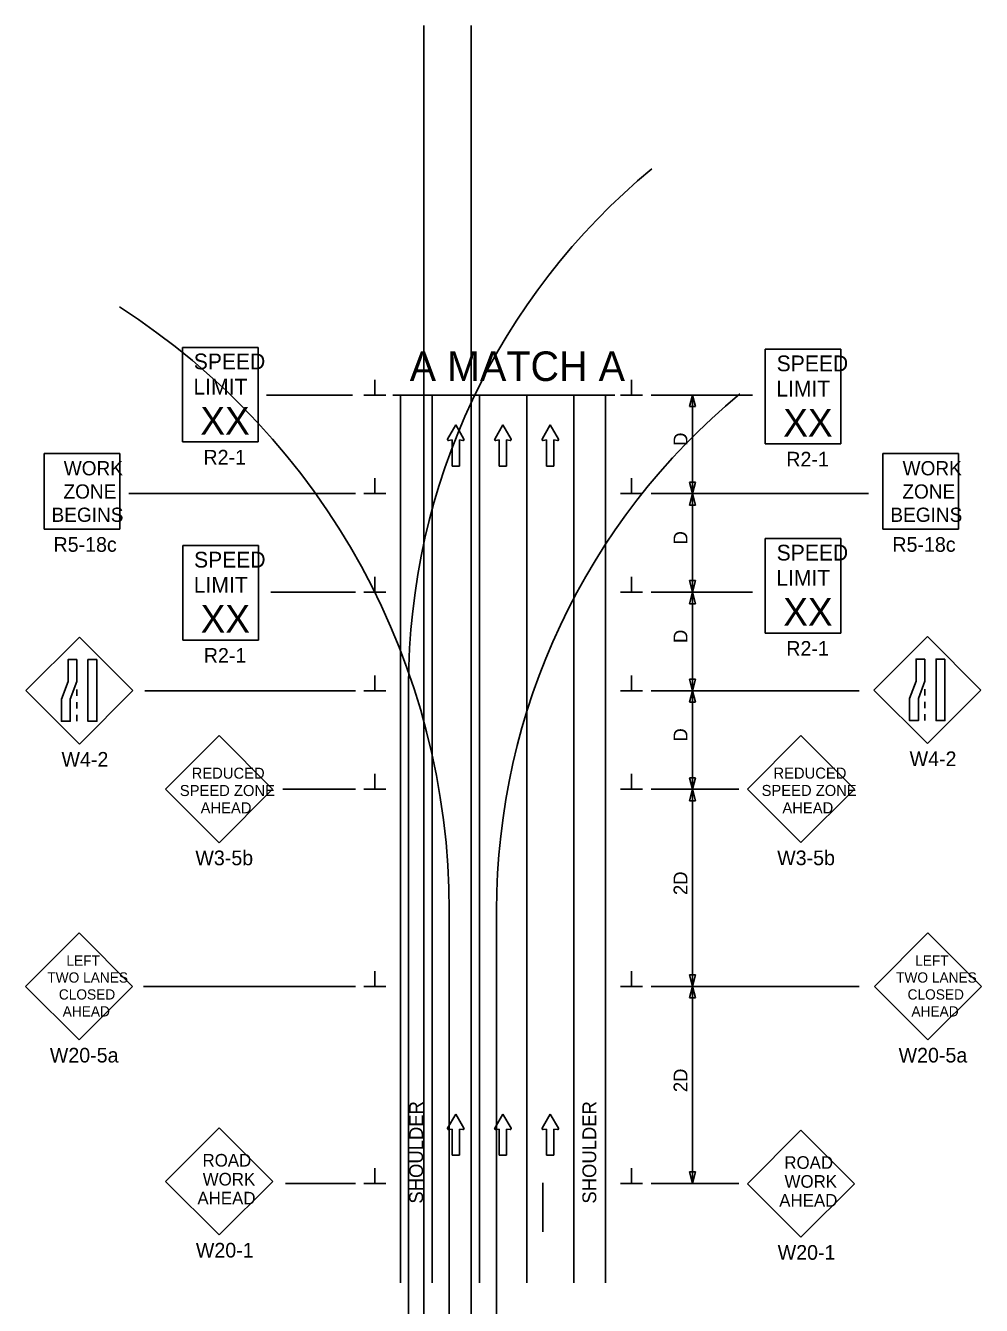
# Model space of a CAD drawing. Extents: x 16452 to 19508, y 5713 to 7079.
# Drawn here: x 17853 to 18337, y 6430 to 7079 of the extents above; entities that cross this region are included whole.
import ezdxf

# ---------------------------------------------------------------- set-up
doc = ezdxf.new("R2010")
doc.units = 0
for name, color, linetype in [('ALI_LEGAL_EX', 7, 'Continuous'), ('MT_SCRATCH_LEVEL_E', 7, 'Continuous'), ('PAVT_EDGE_EX', 7, 'Continuous'), ('TRAFFIC_SIGNS_PR', 7, 'Continuous'), ('TYPICAL_TEXT_DIMEN_PR', 7, 'Continuous')]:
    doc.layers.add(name, color=color, linetype=linetype)

msp = doc.modelspace()

# ---------------------------------------------------------------- linework, layer by layer
at = {"layer": 'ALI_LEGAL_EX'}
for p, q in [((18054.48, 7078.99), (18054.48, 6260.86)), ((18078.48, 7078.99), (18078.48, 6260.86)), ((18054.48, 6981.91), (18054.48, 6118)), ((18078.48, 6981.91), (18078.48, 6118)), ((18082.72, 6441.2), (18082.72, 6891.55)), ((18106.72, 6441.2), (18106.72, 6891.55)), ((18046.81, 6243.91), (18046.81, 6744.25)), ((18067.45, 6129.67), (18067.45, 6630.02)), ((18091.45, 6129.67), (18091.45, 6630.02))]:
    msp.add_line(p, q, dxfattribs=at)
for points in [[(18082.81, 6871.42), (18082.81, 6846.42)], [(18082.72, 6841.2), (18082.72, 6866.2)], [(18106.72, 6841.2), (18106.72, 6866.2)], [(18082.72, 6741.2), (18082.72, 6766.2)], [(18106.72, 6741.2), (18106.72, 6766.2)], [(18082.72, 6641.2), (18082.72, 6666.2)], [(18106.72, 6641.2), (18106.72, 6666.2)], [(18082.72, 6541.2), (18082.72, 6566.2)], [(18106.72, 6541.2), (18106.72, 6566.2)], [(18082.81, 6521.86), (18082.81, 6496.86)], [(18114.95, 6491.99), (18114.95, 6466.99)], [(18082.72, 6441.2), (18082.72, 6466.2)], [(18106.72, 6441.2), (18106.72, 6466.2)]]:
    msp.add_lwpolyline(points, dxfattribs=at)
for centre, radius, start, end in [((18386.81, 6744.25), 340, 129.56655, 180), ((17703.45, 6630.02), 364, 0, 57.29578), ((18431.45, 6630.02), 340, 129.56655, 180)]:
    msp.add_arc(centre, radius, start, end, dxfattribs=at)
at = {"layer": 'MT_SCRATCH_LEVEL_E'}
for p, q in [((18070.73, 6876.38), (18066.62, 6869.14)), ((18074.88, 6869.14), (18070.73, 6876.38)), ((18094.64, 6876.38), (18090.53, 6869.14)), ((18098.78, 6869.14), (18094.64, 6876.38)), ((18118.69, 6876.38), (18114.58, 6869.14)), ((18122.84, 6869.14), (18118.69, 6876.38)), ((18067.1, 6868.46), (18068.88, 6868.77)), ((18068.88, 6868.77), (18068.88, 6855.51)), ((18072.62, 6855.51), (18072.62, 6868.77)), ((18072.62, 6868.77), (18074.4, 6868.46)), ((18091.01, 6868.46), (18092.78, 6868.77)), ((18092.78, 6868.77), (18092.78, 6855.51)), ((18096.53, 6855.51), (18096.53, 6868.77)), ((18096.53, 6868.77), (18098.3, 6868.46)), ((18115.06, 6868.46), (18116.84, 6868.77)), ((18116.84, 6868.77), (18116.84, 6855.51)), ((18120.58, 6855.51), (18120.58, 6868.77)), ((18120.58, 6868.77), (18122.36, 6868.46)), ((18068.88, 6855.51), (18072.62, 6855.51)), ((18092.78, 6855.51), (18096.53, 6855.51)), ((18116.84, 6855.51), (18120.58, 6855.51)), ((18070.73, 6526.83), (18066.62, 6519.59)), ((18074.88, 6519.59), (18070.73, 6526.83)), ((18094.64, 6526.83), (18090.53, 6519.59)), ((18098.78, 6519.59), (18094.64, 6526.83)), ((18118.69, 6526.83), (18114.58, 6519.59)), ((18122.84, 6519.59), (18118.69, 6526.83)), ((18067.1, 6518.9), (18068.88, 6519.22)), ((18068.88, 6519.22), (18068.88, 6505.96)), ((18072.62, 6505.96), (18072.62, 6519.22)), ((18072.62, 6519.22), (18074.4, 6518.9)), ((18091.01, 6518.9), (18092.78, 6519.22)), ((18092.78, 6519.22), (18092.78, 6505.96)), ((18096.53, 6505.96), (18096.53, 6519.22)), ((18096.53, 6519.22), (18098.3, 6518.9)), ((18115.06, 6518.9), (18116.84, 6519.22)), ((18116.84, 6519.22), (18116.84, 6505.96)), ((18120.58, 6505.96), (18120.58, 6519.22)), ((18120.58, 6519.22), (18122.36, 6518.9)), ((18068.88, 6505.96), (18072.62, 6505.96)), ((18092.78, 6505.96), (18096.53, 6505.96)), ((18116.84, 6505.96), (18120.58, 6505.96))]:
    msp.add_line(p, q, dxfattribs=at)
for centre, start, end in [((18067.03, 6868.91), 150.42484, 279.96381), ((18074.47, 6868.91), 260.03619, 29.77312), ((18090.93, 6868.91), 150.42484, 279.96381), ((18098.37, 6868.91), 260.03619, 29.77312), ((18114.99, 6868.91), 150.42484, 279.96381), ((18122.43, 6868.91), 260.03619, 29.77312), ((18067.03, 6519.36), 150.42484, 279.96381), ((18074.47, 6519.36), 260.03619, 29.77312), ((18090.93, 6519.36), 150.42484, 279.96381), ((18098.37, 6519.36), 260.03619, 29.77312), ((18114.99, 6519.36), 150.42484, 279.96381), ((18122.43, 6519.36), 260.03619, 29.77312)]:
    msp.add_arc(centre, 0.463, start, end, dxfattribs=at)
at = {"layer": 'PAVT_EDGE_EX'}
for p, q in [((18042.72, 6891.55), (18042.72, 6441.2)), ((18058.72, 6891.55), (18058.72, 6441.2)), ((18130.72, 6891.55), (18130.72, 6441.2)), ((18146.72, 6891.55), (18146.72, 6441.2))]:
    msp.add_line(p, q, dxfattribs=at)
at = {"layer": 'TRAFFIC_SIGNS_PR'}
for p, q in [((17932.09, 6915.75), (17970.49, 6915.75)), ((17932.09, 6867.75), (17932.09, 6915.75)), ((17970.49, 6867.75), (17970.49, 6915.75)), ((18227.77, 6914.76), (18266.17, 6914.76)), ((18227.77, 6866.76), (18227.77, 6914.76)), ((18266.17, 6866.76), (18266.17, 6914.76)), ((17932.09, 6867.75), (17970.49, 6867.75)), ((18227.77, 6866.76), (18266.17, 6866.76)), ((17861.89, 6823.48), (17861.89, 6861.88)), ((17861.89, 6861.88), (17900.29, 6861.88)), ((17900.29, 6823.48), (17900.29, 6861.88)), ((18287.43, 6823.48), (18287.43, 6861.88)), ((18287.43, 6861.88), (18325.83, 6861.88)), ((18325.83, 6823.48), (18325.83, 6861.88)), ((17861.89, 6823.48), (17900.29, 6823.48)), ((18227.77, 6818.77), (18266.17, 6818.77)), ((18227.77, 6770.77), (18227.77, 6818.77)), ((18266.17, 6770.77), (18266.17, 6818.77)), ((18287.43, 6823.48), (18325.83, 6823.48)), ((17932.24, 6815.2), (17970.64, 6815.2)), ((17932.24, 6767.2), (17932.24, 6815.2)), ((17970.64, 6767.2), (17970.64, 6815.2)), ((17879.8, 6768.78), (17852.64, 6741.63)), ((17906.95, 6741.63), (17879.8, 6768.78)), ((17932.24, 6767.2), (17970.64, 6767.2)), ((18227.77, 6770.77), (18266.17, 6770.77)), ((18310.03, 6769.06), (18282.87, 6741.91)), ((18337.18, 6741.91), (18310.03, 6769.06)), ((17852.64, 6741.63), (17879.8, 6714.47)), ((17878.55, 6742.12), (17878.55, 6738.92)), ((17879.8, 6714.47), (17906.95, 6741.63)), ((18282.87, 6741.91), (18310.03, 6714.76)), ((18308.78, 6742.4), (18308.78, 6739.2)), ((18310.03, 6714.76), (18337.18, 6741.91)), ((17878.55, 6735.72), (17878.55, 6732.52)), ((18308.78, 6736), (18308.78, 6732.8)), ((17878.55, 6729.32), (17878.55, 6726.12)), ((18308.78, 6729.6), (18308.78, 6726.4)), ((17950.71, 6718.78), (17923.56, 6691.63)), ((17977.86, 6691.63), (17950.71, 6718.78)), ((18245.84, 6718.81), (18218.69, 6691.66)), ((18273, 6691.66), (18245.84, 6718.81)), ((17923.56, 6691.63), (17950.71, 6664.47)), ((17950.71, 6664.47), (17977.86, 6691.63)), ((18218.69, 6691.66), (18245.84, 6664.5)), ((18245.84, 6664.5), (18273, 6691.66)), ((17879.69, 6618.7), (17852.54, 6591.55)), ((17906.84, 6591.55), (17879.69, 6618.7)), ((18310.24, 6618.7), (18283.09, 6591.55)), ((18337.39, 6591.55), (18310.24, 6618.7)), ((17852.54, 6591.55), (17879.69, 6564.4)), ((17879.69, 6564.4), (17906.84, 6591.55)), ((18283.09, 6591.55), (18310.24, 6564.4)), ((18310.24, 6564.4), (18337.39, 6591.55)), ((17950.74, 6519.77), (17923.59, 6492.62)), ((17977.9, 6492.62), (17950.74, 6519.77)), ((18245.88, 6518.64), (18218.73, 6491.48)), ((18273.03, 6491.48), (18245.88, 6518.64)), ((17923.59, 6492.62), (17950.74, 6465.47)), ((17950.74, 6465.47), (17977.9, 6492.62)), ((18218.73, 6491.48), (18245.88, 6464.33)), ((18245.88, 6464.33), (18273.03, 6491.48))]:
    msp.add_line(p, q, dxfattribs=at)
for points in [[(17878.55, 6757.36), (17878.55, 6746.18), (17875.2, 6737.3), (17875.2, 6726.12), (17870.71, 6726.12), (17870.71, 6737.3), (17874.05, 6746.18), (17874.05, 6757.36)], [(17888.68, 6757.36), (17888.68, 6726.12), (17884.19, 6726.12), (17884.19, 6757.36)], [(18308.78, 6757.65), (18308.78, 6746.46), (18305.43, 6737.58), (18305.43, 6726.4), (18300.94, 6726.4), (18300.94, 6737.58), (18304.28, 6746.46), (18304.28, 6757.65)], [(18318.91, 6757.65), (18318.91, 6726.4), (18314.42, 6726.4), (18314.42, 6757.65)]]:
    msp.add_lwpolyline(points, close=True, dxfattribs=at)
at = {"layer": 'TYPICAL_TEXT_DIMEN_PR'}
for p, q in [((18029.69, 6891.55), (18029.69, 6899.34)), ((18159.94, 6891.55), (18159.94, 6899.34)), ((17974.8, 6891.55), (18018.42, 6891.55)), ((18024.06, 6891.55), (18035.31, 6891.55)), ((18038.79, 6891.55), (18151.44, 6891.55)), ((18165.56, 6891.55), (18154.31, 6891.55)), ((18169.81, 6891.55), (18221.23, 6891.55)), ((18189.24, 6885.69), (18190.81, 6891.55)), ((18190.81, 6891.55), (18190.81, 6841.55)), ((18190.81, 6891.55), (18192.39, 6885.69)), ((18190.81, 6885.69), (18189.24, 6885.69)), ((18192.39, 6885.69), (18190.81, 6885.69)), ((18029.69, 6841.55), (18029.69, 6849.34)), ((18159.94, 6841.55), (18159.94, 6849.34)), ((18190.81, 6841.55), (18189.24, 6847.41)), ((18189.24, 6847.41), (18190.81, 6847.41)), ((18190.81, 6847.41), (18192.39, 6847.41)), ((18192.39, 6847.41), (18190.81, 6841.55)), ((18019.81, 6841.55), (17904.88, 6841.55)), ((18024.06, 6841.55), (18035.31, 6841.55)), ((18165.56, 6841.55), (18154.31, 6841.55)), ((18169.81, 6841.55), (18280.08, 6841.55)), ((18189.24, 6835.69), (18190.81, 6841.55)), ((18190.81, 6841.55), (18192.39, 6835.69)), ((18190.81, 6841.55), (18190.81, 6791.55)), ((18190.81, 6835.69), (18189.24, 6835.69)), ((18192.39, 6835.69), (18190.81, 6835.69)), ((18029.69, 6791.55), (18029.69, 6799.34)), ((18159.94, 6791.55), (18159.94, 6799.34)), ((18019.81, 6791.55), (17976.96, 6791.55)), ((18024.06, 6791.55), (18035.31, 6791.55)), ((18165.56, 6791.55), (18154.31, 6791.55)), ((18169.81, 6791.55), (18221.23, 6791.55)), ((18190.81, 6791.55), (18189.24, 6797.41)), ((18189.24, 6797.41), (18190.81, 6797.41)), ((18189.24, 6785.69), (18190.81, 6791.55)), ((18190.81, 6797.41), (18192.39, 6797.41)), ((18192.39, 6797.41), (18190.81, 6791.55)), ((18190.81, 6791.55), (18190.81, 6741.55)), ((18190.81, 6791.55), (18192.39, 6785.69)), ((18190.81, 6785.69), (18189.24, 6785.69)), ((18192.39, 6785.69), (18190.81, 6785.69)), ((18029.69, 6741.55), (18029.69, 6749.34)), ((18159.94, 6741.55), (18159.94, 6749.34)), ((18190.81, 6741.55), (18189.24, 6747.41)), ((18189.24, 6747.41), (18190.81, 6747.41)), ((18190.81, 6747.41), (18192.39, 6747.41)), ((18192.39, 6747.41), (18190.81, 6741.55)), ((17913.01, 6741.55), (18019.81, 6741.55)), ((18024.06, 6741.55), (18035.31, 6741.55)), ((18165.56, 6741.55), (18154.31, 6741.55)), ((18169.81, 6741.55), (18275.33, 6741.55)), ((18189.24, 6735.69), (18190.81, 6741.55)), ((18190.81, 6741.55), (18190.81, 6691.55)), ((18190.81, 6741.55), (18192.39, 6735.69)), ((18190.81, 6735.69), (18189.24, 6735.69)), ((18192.39, 6735.69), (18190.81, 6735.69)), ((18029.69, 6691.55), (18029.69, 6699.34)), ((18159.94, 6691.55), (18159.94, 6699.34)), ((18190.81, 6691.55), (18189.24, 6697.41)), ((18189.24, 6697.41), (18190.81, 6697.41)), ((18190.81, 6697.41), (18192.39, 6697.41)), ((18192.39, 6697.41), (18190.81, 6691.55)), ((17983.08, 6691.55), (18019.81, 6691.55)), ((18024.06, 6691.55), (18035.31, 6691.55)), ((18165.56, 6691.55), (18154.31, 6691.55)), ((18169.81, 6691.55), (18214.3, 6691.55)), ((18189.24, 6685.69), (18190.81, 6691.55)), ((18190.81, 6691.55), (18190.81, 6591.55)), ((18190.81, 6691.55), (18192.39, 6685.69)), ((18190.81, 6685.69), (18189.24, 6685.69)), ((18192.39, 6685.69), (18190.81, 6685.69)), ((18029.69, 6591.55), (18029.69, 6599.34)), ((18159.94, 6591.55), (18159.94, 6599.34)), ((18190.81, 6591.55), (18189.24, 6597.41)), ((18189.24, 6597.41), (18190.81, 6597.41)), ((18190.81, 6597.41), (18192.39, 6597.41)), ((18192.39, 6597.41), (18190.81, 6591.55)), ((18019.81, 6591.55), (17912.38, 6591.55)), ((18024.06, 6591.55), (18035.31, 6591.55)), ((18165.56, 6591.55), (18154.31, 6591.55)), ((18169.81, 6591.55), (18275.33, 6591.55)), ((18189.24, 6585.69), (18190.81, 6591.55)), ((18190.81, 6591.55), (18190.81, 6491.55)), ((18190.81, 6591.55), (18192.39, 6585.69)), ((18190.81, 6585.69), (18189.24, 6585.69)), ((18192.39, 6585.69), (18190.81, 6585.69)), ((18029.69, 6491.55), (18029.69, 6499.34)), ((18159.94, 6491.55), (18159.94, 6499.34)), ((18190.81, 6491.55), (18189.24, 6497.41)), ((18189.24, 6497.41), (18190.81, 6497.41)), ((18190.81, 6497.41), (18192.39, 6497.41)), ((18192.39, 6497.41), (18190.81, 6491.55)), ((18019.81, 6491.55), (17984.36, 6491.55)), ((18024.06, 6491.55), (18035.31, 6491.55)), ((18165.56, 6491.55), (18154.31, 6491.55)), ((18169.81, 6491.55), (18214.33, 6491.55))]:
    msp.add_line(p, q, dxfattribs=at)

# ---------------------------------------------------------------- texts
at = {"layer": 'TRAFFIC_SIGNS_PR'}
for s, height, p in [('SPEED', 8, (17937.85, 6904.62)), ('SPEED', 8, (18233.53, 6903.63)), ('LIMIT', 8, (17937.69, 6891.82)), ('LIMIT', 8, (18233.37, 6890.83)), ('XX', 14.031, (17941.2, 6871.51)), ('XX', 14.031, (18236.88, 6870.52)), ('R2-1', 7.44, (17942.76, 6856.31)), ('R2-1', 7.44, (18238.44, 6855.32)), ('WORK', 7.217, (17871.89, 6850.84)), ('WORK', 7.217, (18297.43, 6850.84)), ('ZONE', 7.217, (17871.77, 6839.03)), ('ZONE', 7.217, (18297.31, 6839.03)), ('BEGINS', 7.217, (17865.7, 6827.23)), ('BEGINS', 7.217, (18291.24, 6827.23)), ('R5-18c', 7.44, (17866.7, 6812.04)), ('R5-18c', 7.44, (18292.24, 6812.04)), ('SPEED', 8, (17938.01, 6804.06)), ('SPEED', 8, (18233.53, 6807.63)), ('LIMIT', 8, (17937.85, 6791.26)), ('LIMIT', 8, (18233.37, 6794.83)), ('XX', 14.031, (17941.35, 6770.96)), ('XX', 14.031, (18236.88, 6774.52)), ('R2-1', 7.44, (18238.44, 6759.32)), ('R2-1', 7.44, (17942.92, 6755.76)), ('W4-2', 7.44, (17870.75, 6703.03)), ('W4-2', 7.44, (18300.98, 6703.32)), ('REDUCED', 5.6, (17936.77, 6696.94)), ('REDUCED', 5.6, (18231.9, 6696.97)), ('SPEED ZONE', 5.6, (17930.76, 6688.14)), ('SPEED ZONE', 5.6, (18225.89, 6688.17)), ('AHEAD', 5.6, (17941.32, 6679.34)), ('AHEAD', 5.6, (18236.45, 6679.37)), ('W3-5b', 7.44, (17938.66, 6653.04)), ('W3-5b', 7.44, (18233.8, 6653.07)), ('LEFT', 5.2, (17873.23, 6602.09)), ('LEFT', 5.2, (18303.78, 6602.09)), ('TWO LANES', 5.2, (17863.55, 6593.49)), ('TWO LANES', 5.2, (18294.1, 6593.49)), ('CLOSED', 5.2, (17869.4, 6584.89)), ('CLOSED', 5.2, (18299.95, 6584.89)), ('AHEAD', 5.2, (17871.35, 6576.29)), ('AHEAD', 5.2, (18301.9, 6576.29)), ('W20-5a', 7.44, (17864.83, 6552.96)), ('W20-5a', 7.44, (18295.38, 6552.96)), ('ROAD', 6.4, (17942.29, 6500.16)), ('ROAD', 6.4, (18237.42, 6499.02)), ('WORK', 6.4, (17942.39, 6490.56)), ('WORK', 6.4, (18237.53, 6489.42)), ('AHEAD', 6.4, (17939.7, 6480.96)), ('AHEAD', 6.4, (18234.84, 6479.82)), ('W20-1', 7.44, (17938.91, 6454.03)), ('W20-1', 7.44, (18234.05, 6452.89))]:
    msp.add_text(s, height=height, dxfattribs=at).set_placement(p)
at = {"layer": 'TYPICAL_TEXT_DIMEN_PR'}
msp.add_text('A MATCH A', height=15, dxfattribs=at).set_placement((18047.38, 6898.69))
for s, p in [('D', (18188.26, 6865.77)), ('D', (18188.26, 6815.77)), ('D', (18188.26, 6765.77)), ('D', (18188.26, 6715.77)), ('2D', (18188.26, 6637.91)), ('2D', (18188.26, 6537.91)), ('SHOULDER', (18054.15, 6481.37)), ('SHOULDER', (18142.01, 6481.37))]:
    msp.add_text(s, height=7, rotation=90, dxfattribs=at).set_placement(p)

doc.saveas('drawing.dxf')
